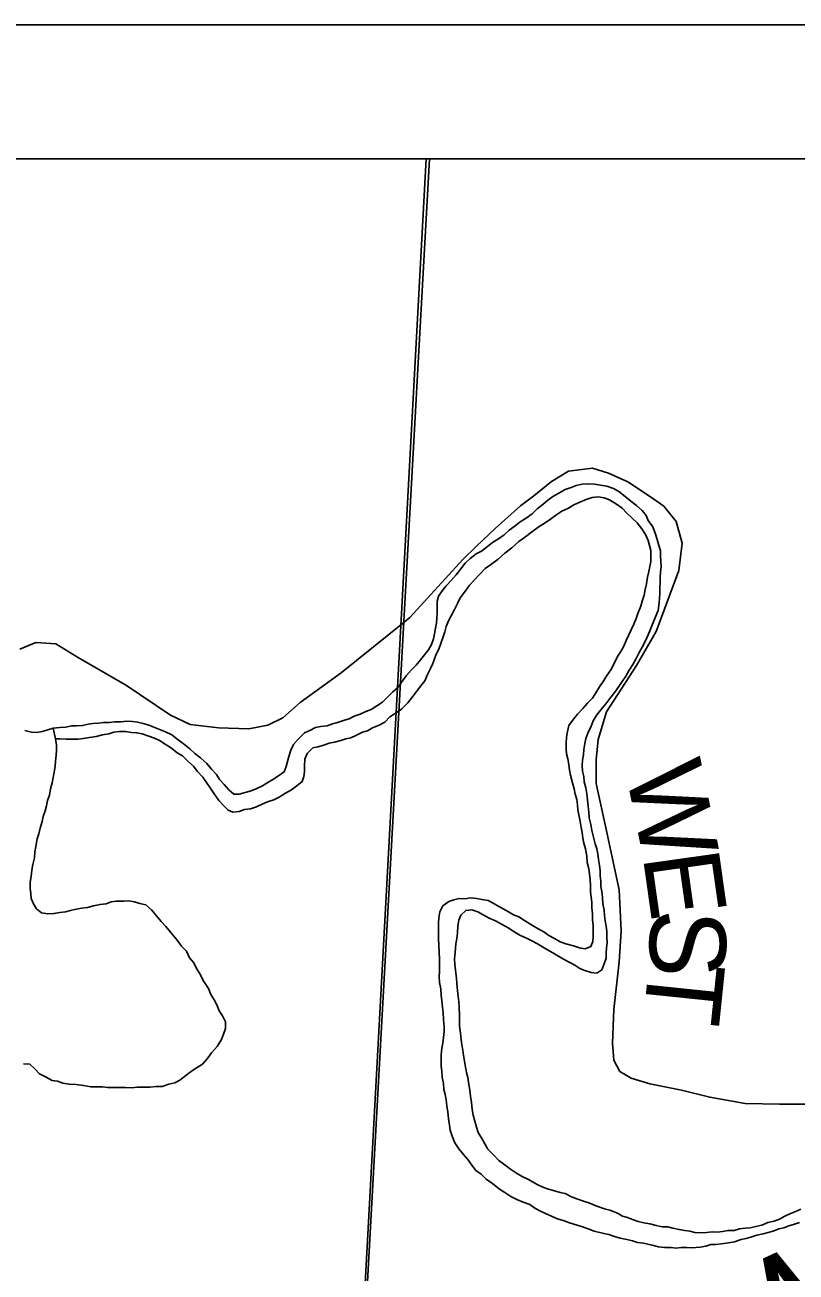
# Model space of a CAD drawing. Extents: x -20.2 to 34, y 0 to 22.
# Drawn here: x 7.849 to 8.424, y 20.069 to 21 of the extents above; entities that cross this region are included whole.
import ezdxf

# ---------------------------------------------------------------- set-up
doc = ezdxf.new("R2010")
doc.units = 0
for name, color, linetype in [('Default', 7, 'Continuous'), ('GM_X_Major_River', 7, 'Continuous'), ('GM_X_Minor_River', 7, 'Continuous'), ('GM_X_Minor_River_Text', 7, 'Continuous'), ('GM_X_Township_Road', 7, 'Continuous'), ('GM_X_Township_Road_Text', 7, 'Continuous'), ('SH_Cut_Line', 7, 'Continuous'), ('SH_Data', 7, 'Continuous')]:
    doc.layers.add(name, color=color, linetype=linetype)

msp = doc.modelspace()

# ---------------------------------------------------------------- linework, layer by layer
at = {"layer": 'Default'}
for points in [[(8.15084, 20.9), (2.1, 20.9), (2.1, 19.2514), (2.92528, 19.19513), (4.08404, 19.12989), (4.12898, 19.12845), (4.49998, 19.10635), (4.57534, 19.10322), (5.07163, 19.0751), (5.61682, 19.0426), (5.62797, 19.04192), (5.90057, 19.02599), (6.53318, 18.99275), (7.38712, 18.94649), (7.53952, 18.93824), (7.80715, 18.91995), (8.043, 18.90974), (8.04849, 19.09144), (8.07091, 19.45221), (8.1316, 20.55479)], [(8.14837, 20.9), (7.0959, 20.9), (7.04086, 20.01146), (8.09719, 19.95555)], [(8.9, 19.92008), (8.9, 20.9), (8.14837, 20.9), (8.09719, 19.95555)]]:
    msp.add_lwpolyline(points, close=True, dxfattribs=at)
msp.add_lwpolyline([(8.9, 14.81759), (8.9, 20.9), (8.15084, 20.9), (8.1316, 20.55479), (8.07091, 19.45221), (8.04849, 19.09144), (8.043, 18.90974), (7.80715, 18.91995), (7.53952, 18.93824), (7.38712, 18.94649), (6.53318, 18.99275), (5.90057, 19.02599), (5.87099, 18.53836), (5.80691, 17.48436), (5.78313, 17.24828), (5.78116, 17.15273), (5.73681, 16.42062)], dxfattribs=at)
at = {"layer": 'GM_X_Major_River'}
for points in [[(8.28122, 20.29949), (8.28269, 20.30368), (8.28265, 20.30748), (8.28298, 20.31129), (8.28332, 20.31509), (8.28327, 20.31889), (8.28321, 20.32383), (8.28279, 20.32762), (8.28199, 20.33142), (8.28156, 20.33559), (8.28113, 20.33938), (8.28031, 20.34431), (8.27988, 20.34887), (8.27945, 20.35342), (8.27864, 20.35721), (8.2786, 20.36101), (8.27817, 20.36519), (8.27813, 20.36899), (8.2777, 20.37278), (8.27689, 20.37733), (8.27646, 20.3815), (8.27565, 20.38529), (8.27447, 20.38908), (8.27327, 20.394), (8.27208, 20.39893), (8.27126, 20.40348), (8.27007, 20.4084), (8.26964, 20.41258), (8.2692, 20.41713), (8.26877, 20.42169), (8.26834, 20.42624), (8.26753, 20.43079), (8.26633, 20.43534), (8.26591, 20.43913), (8.2651, 20.4433), (8.26467, 20.44748), (8.265, 20.45128), (8.26571, 20.45547), (8.26605, 20.45927), (8.26675, 20.46384), (8.26747, 20.46765), (8.26894, 20.47147), (8.27154, 20.47682), (8.27301, 20.48064), (8.27561, 20.48523), (8.2786, 20.48907), (8.28235, 20.4933), (8.28534, 20.49752), (8.28908, 20.50212), (8.29207, 20.50634), (8.29468, 20.51017), (8.29729, 20.514), (8.29989, 20.5186), (8.3025, 20.52281), (8.30473, 20.52664), (8.30733, 20.53161), (8.30956, 20.53582), (8.31216, 20.54041), (8.314, 20.545), (8.31585, 20.5492), (8.31769, 20.55416), (8.31954, 20.55836), (8.32138, 20.56295), (8.3221, 20.56676), (8.32242, 20.5717), (8.32274, 20.57626), (8.3227, 20.58006), (8.32303, 20.58387), (8.32298, 20.58805), (8.32332, 20.59185), (8.32365, 20.59565), (8.32361, 20.59945), (8.32318, 20.60401), (8.32313, 20.60781), (8.32195, 20.61159), (8.32075, 20.61614), (8.31918, 20.62068), (8.31761, 20.6256), (8.31414, 20.63012), (8.31257, 20.63389), (8.30949, 20.63766), (8.30527, 20.6414), (8.30106, 20.64477), (8.29684, 20.64814), (8.29224, 20.65188), (8.28804, 20.65411), (8.28308, 20.65595), (8.27852, 20.65665), (8.27396, 20.65735), (8.2694, 20.65767), (8.26485, 20.65724), (8.2603, 20.65642), (8.25653, 20.65485), (8.25199, 20.65327), (8.24746, 20.65056), (8.24294, 20.64822), (8.23917, 20.64551), (8.23542, 20.64205), (8.23128, 20.63896), (8.22753, 20.63511), (8.22301, 20.63201)], [(8.23258, 20.62567), (8.23635, 20.628), (8.24124, 20.6311), (8.24576, 20.63458), (8.24952, 20.63729), (8.25405, 20.63924), (8.25858, 20.64196), (8.26311, 20.64392), (8.26764, 20.64587), (8.27217, 20.64745), (8.27672, 20.64789), (8.28129, 20.64718), (8.2851, 20.64571), (8.29046, 20.64236), (8.29467, 20.63937), (8.29813, 20.63561), (8.30196, 20.63224), (8.3058, 20.62849), (8.30927, 20.62397), (8.31198, 20.61983), (8.31393, 20.61529), (8.31511, 20.61151), (8.31592, 20.60772), (8.31597, 20.60354), (8.31601, 20.59974), (8.3153, 20.59593), (8.31459, 20.59212), (8.3135, 20.58793), (8.3128, 20.58298), (8.31171, 20.57879), (8.31099, 20.5746), (8.30953, 20.57002), (8.30844, 20.56621), (8.30622, 20.56086), (8.30513, 20.55704), (8.30328, 20.55284), (8.30143, 20.54864), (8.29958, 20.54481), (8.29773, 20.54061), (8.29588, 20.53641), (8.29365, 20.53258), (8.29104, 20.52875), (8.28845, 20.52301), (8.28622, 20.51881), (8.28324, 20.51459), (8.281, 20.51076), (8.27764, 20.50616), (8.27504, 20.50157), (8.27243, 20.49773), (8.26868, 20.49389), (8.26531, 20.49004), (8.26118, 20.48581), (8.25819, 20.48197), (8.25483, 20.47737), (8.25374, 20.4728), (8.25303, 20.46861), (8.25271, 20.46405), (8.25276, 20.45987), (8.25318, 20.45607), (8.25398, 20.45228), (8.25479, 20.44811), (8.25522, 20.44394), (8.25603, 20.44015), (8.25761, 20.43447), (8.2588, 20.42992), (8.25961, 20.42613), (8.2608, 20.42197), (8.26122, 20.41817), (8.26164, 20.41438), (8.26246, 20.40945), (8.26327, 20.40566), (8.26408, 20.40111), (8.26488, 20.39732), (8.26531, 20.39314), (8.26612, 20.38936), (8.2673, 20.38519), (8.26813, 20.37988), (8.26856, 20.37495), (8.26976, 20.3704), (8.27018, 20.36661), (8.27062, 20.36205), (8.27104, 20.35788), (8.2711, 20.35294), (8.27153, 20.34914), (8.27195, 20.34535), (8.272, 20.34117), (8.27243, 20.33661), (8.27249, 20.33206), (8.27291, 20.32826), (8.27296, 20.32408), (8.27301, 20.3199), (8.27268, 20.3161), (8.2712, 20.31228), (8.26705, 20.31071), (8.26286, 20.31142), (8.25829, 20.31288), (8.25258, 20.31433), (8.24839, 20.31579), (8.24418, 20.3184), (8.23998, 20.32063), (8.23615, 20.32324)], [(8.22301, 20.63201), (8.21849, 20.62929), (8.21473, 20.62621), (8.21021, 20.62311), (8.20646, 20.61964), (8.20232, 20.61655), (8.19779, 20.61384), (8.19403, 20.61075), (8.18952, 20.60727), (8.18574, 20.60532), (8.18123, 20.60185), (8.17748, 20.59838), (8.17411, 20.59416), (8.17075, 20.58956), (8.167, 20.58533), (8.16325, 20.58148), (8.16026, 20.57764), (8.15765, 20.57381), (8.15656, 20.57), (8.1566, 20.56582), (8.15666, 20.56126), (8.15632, 20.55746), (8.15599, 20.55365), (8.15528, 20.54984), (8.15457, 20.54565), (8.15385, 20.54184), (8.15238, 20.53765), (8.15015, 20.53382), (8.14716, 20.52998), (8.14417, 20.52614), (8.1408, 20.5223), (8.13705, 20.51845), (8.1333, 20.51423), (8.12994, 20.50963), (8.12733, 20.50579), (8.12357, 20.50232), (8.11944, 20.49847), (8.11569, 20.49463), (8.11155, 20.49191), (8.1074, 20.4892), (8.10325, 20.48763), (8.09909, 20.48568), (8.09456, 20.4841), (8.09078, 20.48215), (8.08662, 20.48096), (8.08209, 20.47939), (8.0783, 20.47858), (8.07452, 20.47701), (8.06959, 20.47657), (8.06581, 20.47576), (8.06203, 20.47381), (8.0575, 20.47186), (8.053, 20.46724), (8.04926, 20.46301), (8.04741, 20.45881), (8.04594, 20.45423), (8.04485, 20.45042), (8.04376, 20.4466), (8.04228, 20.44279), (8.03814, 20.43969), (8.034, 20.43698), (8.03023, 20.43465), (8.02608, 20.43232), (8.02193, 20.43037), (8.01778, 20.42842), (8.01324, 20.42722), (8.0087, 20.42602), (8.0047, 20.42607), (8.00107, 20.42935), (7.9976, 20.43311), (7.99414, 20.43686), (7.99182, 20.44063), (7.98798, 20.44476), (7.98451, 20.4489), (7.97991, 20.45302), (7.97569, 20.45639), (7.97186, 20.45976), (7.96687, 20.46388), (7.96228, 20.46724), (7.95845, 20.47023), (7.95387, 20.47246), (7.95005, 20.47393), (7.94624, 20.4754), (7.94128, 20.47762), (7.93709, 20.4787), (7.9329, 20.47979), (7.9291, 20.48012), (7.92492, 20.48045), (7.92037, 20.48001), (7.91582, 20.47996), (7.91203, 20.47953), (7.90747, 20.47947), (7.90368, 20.47904), (7.89955, 20.47885), (7.8961, 20.47819), (7.89193, 20.47738), (7.88738, 20.47694), (7.88359, 20.47689), (7.87942, 20.47608), (7.87487, 20.47564), (7.86994, 20.4752)], [(7.86994, 20.4752), (7.87156, 20.46724), (7.87497, 20.46729), (7.87953, 20.46696), (7.88408, 20.46702), (7.88864, 20.46708), (7.89243, 20.4675), (7.89697, 20.46832), (7.9019, 20.46914), (7.90682, 20.47034), (7.91137, 20.47116), (7.91515, 20.47235), (7.91932, 20.47278), (7.92387, 20.47284), (7.92844, 20.47214), (7.93224, 20.4718), (7.93642, 20.4711), (7.94061, 20.46963), (7.94557, 20.46779), (7.94939, 20.46594), (7.9536, 20.46333), (7.95818, 20.46035), (7.9624, 20.45698), (7.96648, 20.45459), (7.97045, 20.45062), (7.97467, 20.44688), (7.97737, 20.44311), (7.9816, 20.4386), (7.9843, 20.43484), (7.987, 20.43069), (7.9901, 20.42617), (7.99357, 20.42127), (7.99703, 20.41752), (8.00043, 20.41404), (8.00392, 20.41266), (8.00885, 20.41311), (8.01263, 20.41467), (8.01718, 20.41511), (8.02171, 20.41669), (8.02587, 20.41864), (8.03002, 20.42021), (8.03456, 20.42179), (8.03871, 20.42374), (8.04323, 20.42684), (8.04776, 20.42917), (8.0519, 20.43227), (8.05566, 20.43535), (8.05713, 20.43917), (8.05746, 20.44297), (8.05742, 20.44716), (8.05774, 20.4521), (8.05958, 20.4563), (8.06371, 20.46054), (8.0675, 20.46134), (8.07204, 20.46254), (8.07582, 20.46411), (8.07998, 20.46492), (8.08452, 20.46611), (8.0883, 20.4673), (8.09209, 20.46811), (8.09587, 20.46968), (8.10077, 20.4724), (8.10456, 20.47321), (8.10833, 20.47553), (8.11324, 20.4775), (8.11738, 20.47983), (8.12114, 20.48367), (8.12603, 20.48678), (8.1298, 20.48948), (8.13468, 20.4941), (8.13804, 20.49871), (8.14103, 20.50254), (8.1444, 20.50677), (8.14739, 20.51061), (8.14923, 20.51519), (8.15146, 20.51978), (8.15331, 20.5236), (8.15588, 20.53047), (8.15774, 20.53429), (8.15958, 20.53926), (8.16104, 20.54346), (8.16214, 20.54727), (8.16323, 20.55108), (8.16508, 20.55529), (8.16693, 20.55911), (8.16916, 20.56332), (8.17176, 20.56829), (8.17361, 20.57249), (8.17772, 20.57786), (8.18071, 20.58208), (8.18446, 20.58593), (8.18783, 20.58977), (8.19233, 20.59439), (8.19647, 20.5971), (8.20212, 20.60135), (8.20699, 20.60597), (8.21226, 20.60984), (8.21752, 20.61446), (8.22166, 20.61755), (8.22806, 20.6222), (8.23258, 20.62567)], [(8.23615, 20.32324), (8.23195, 20.32547), (8.22774, 20.32807), (8.22162, 20.3318), (8.21742, 20.33441), (8.2136, 20.33588), (8.20864, 20.33886), (8.20252, 20.3422), (8.19832, 20.3448), (8.1945, 20.34666), (8.18993, 20.34736), (8.18613, 20.34807), (8.18119, 20.34877), (8.1774, 20.34796), (8.17284, 20.34829), (8.16906, 20.3471), (8.16528, 20.34591), (8.16076, 20.34281), (8.15854, 20.33822), (8.15783, 20.33366), (8.15749, 20.32985), (8.15754, 20.32605), (8.1576, 20.32149), (8.15764, 20.3177), (8.15769, 20.31351), (8.15814, 20.30782), (8.15819, 20.30326), (8.15824, 20.2987), (8.1583, 20.29376), (8.15797, 20.28996), (8.1584, 20.2854), (8.15921, 20.28086), (8.15965, 20.27592), (8.16008, 20.27175), (8.16052, 20.26719), (8.16094, 20.26302), (8.16139, 20.2577), (8.16182, 20.25277), (8.16187, 20.24897), (8.16117, 20.2444), (8.16083, 20.24021), (8.16012, 20.23641), (8.15942, 20.23146), (8.15946, 20.22766), (8.15952, 20.2231), (8.15994, 20.2193), (8.16038, 20.21475), (8.16119, 20.2102), (8.16162, 20.20564), (8.16243, 20.20186), (8.16323, 20.19807), (8.16367, 20.19313), (8.16448, 20.18896), (8.16492, 20.18365), (8.16573, 20.1791), (8.16616, 20.1753), (8.16773, 20.17076), (8.16968, 20.16585), (8.17278, 20.16133), (8.17624, 20.15719), (8.17932, 20.15343), (8.18241, 20.14929), (8.18549, 20.14514), (8.18932, 20.14253), (8.19316, 20.13878), (8.19775, 20.13542), (8.20312, 20.13131), (8.20695, 20.12869), (8.21153, 20.12571), (8.21612, 20.12349), (8.22069, 20.12165), (8.22565, 20.11981), (8.22948, 20.1172), (8.23368, 20.11497), (8.2375, 20.11312), (8.24246, 20.1109), (8.24628, 20.10905), (8.25123, 20.10759), (8.25542, 20.10612), (8.26114, 20.1043), (8.26494, 20.1032), (8.26914, 20.10174), (8.27371, 20.09989), (8.28095, 20.09808), (8.28475, 20.09737), (8.28895, 20.0959), (8.29313, 20.09482), (8.29808, 20.09374), (8.30227, 20.09265), (8.30608, 20.09156), (8.31064, 20.09086), (8.31711, 20.08942), (8.32168, 20.08834), (8.32624, 20.08763), (8.33118, 20.0877), (8.33498, 20.08736), (8.33877, 20.08779), (8.34294, 20.08784), (8.34674, 20.08751), (8.35281, 20.08797), (8.35698, 20.08878)], [(8.34889, 20.09894), (8.34507, 20.10003), (8.34128, 20.10036), (8.33709, 20.10107), (8.33252, 20.10215), (8.32871, 20.10324), (8.32454, 20.10319), (8.31997, 20.10427), (8.3154, 20.10536), (8.31084, 20.10606), (8.30665, 20.10715), (8.30246, 20.10861), (8.29865, 20.11009), (8.29484, 20.11118), (8.29102, 20.11341), (8.2853, 20.11562), (8.28149, 20.11671), (8.27577, 20.11854), (8.26967, 20.12112), (8.26586, 20.12221), (8.2609, 20.12405), (8.25671, 20.12552), (8.25212, 20.12812), (8.24832, 20.12884), (8.24413, 20.12992), (8.23956, 20.13139), (8.23537, 20.13285), (8.23117, 20.1347), (8.22467, 20.13842), (8.22009, 20.14064), (8.21588, 20.14325), (8.21129, 20.14623), (8.20631, 20.14997), (8.20249, 20.15258), (8.19826, 20.15709), (8.19441, 20.16122), (8.19209, 20.16499), (8.18977, 20.16914), (8.18705, 20.17367), (8.18587, 20.17745), (8.18468, 20.182), (8.18349, 20.18654), (8.18268, 20.19071), (8.18223, 20.19603), (8.18142, 20.20057), (8.18099, 20.20513), (8.18018, 20.2093), (8.17936, 20.21461), (8.17855, 20.2184), (8.17775, 20.22219), (8.17694, 20.22674), (8.17613, 20.23091), (8.1757, 20.23508), (8.17489, 20.23887), (8.17447, 20.24267), (8.17403, 20.2476), (8.17321, 20.25291), (8.17317, 20.25671), (8.17312, 20.26089), (8.17304, 20.26697), (8.17262, 20.27114), (8.17219, 20.27494), (8.17176, 20.27949), (8.17132, 20.28481), (8.17089, 20.2886), (8.17046, 20.2924), (8.16963, 20.29922), (8.16958, 20.30303), (8.1699, 20.30797), (8.17059, 20.31444), (8.1713, 20.31825), (8.17163, 20.32243), (8.17195, 20.32775), (8.17265, 20.33194), (8.17413, 20.33576), (8.17788, 20.33923), (8.18243, 20.33967), (8.18701, 20.3382), (8.19083, 20.33597), (8.19541, 20.33337), (8.19999, 20.33153), (8.20458, 20.32892), (8.20954, 20.32633), (8.21452, 20.32297), (8.21834, 20.32074), (8.2233, 20.31852), (8.22712, 20.31667), (8.23132, 20.31444), (8.23514, 20.31221), (8.23896, 20.30998), (8.24279, 20.30774), (8.24661, 20.30551), (8.25082, 20.3029), (8.25502, 20.30068), (8.25922, 20.29845), (8.26305, 20.29584), (8.26686, 20.29437), (8.27143, 20.2929), (8.27561, 20.29257), (8.27938, 20.2949), (8.28122, 20.29949)], [(8.42802, 20.11627), (8.42348, 20.11431), (8.41971, 20.11275), (8.41593, 20.11118), (8.41216, 20.10885), (8.408, 20.10728), (8.40346, 20.10646), (8.39892, 20.1045), (8.39438, 20.10331), (8.39022, 20.1025), (8.38643, 20.10207), (8.38226, 20.10164), (8.3781, 20.10044), (8.37354, 20.10039), (8.36976, 20.09958), (8.36559, 20.09915), (8.36179, 20.09948), (8.35762, 20.09905), (8.35382, 20.09862), (8.34889, 20.09894)], [(8.35698, 20.08878), (8.36076, 20.08996), (8.36455, 20.09001), (8.36872, 20.09045), (8.37403, 20.09127), (8.37857, 20.09209), (8.38349, 20.09367), (8.38728, 20.09448), (8.39144, 20.09567), (8.39522, 20.09686), (8.39976, 20.09806), (8.40355, 20.09886), (8.40733, 20.10005), (8.41149, 20.10162), (8.41527, 20.10243), (8.41905, 20.104), (8.42321, 20.10519), (8.42699, 20.10638)]]:
    msp.add_lwpolyline(points, dxfattribs=at)
at = {"layer": 'GM_X_Minor_River'}
for points in [[(7.84871, 20.47342), (7.85365, 20.47234), (7.85745, 20.472), (7.862, 20.47282), (7.86994, 20.4752)], [(7.86589, 20.33683), (7.86132, 20.33754), (7.85749, 20.34053), (7.85517, 20.3443), (7.8536, 20.34808), (7.85318, 20.35187), (7.85276, 20.35567), (7.8527, 20.36022), (7.85341, 20.36479), (7.85411, 20.36936), (7.85482, 20.37355), (7.8559, 20.37851), (7.85623, 20.38307), (7.85694, 20.38688), (7.85801, 20.39259), (7.85911, 20.3964), (7.8602, 20.4006), (7.86166, 20.40556), (7.86237, 20.40937), (7.86384, 20.41357), (7.86493, 20.41738), (7.86565, 20.42119), (7.86711, 20.42539), (7.86782, 20.42995), (7.86928, 20.43453), (7.87, 20.43834), (7.87071, 20.44253), (7.87142, 20.44672), (7.87175, 20.45052), (7.87208, 20.45509), (7.87241, 20.45889), (7.87237, 20.46269), (7.87156, 20.46724)], [(7.84785, 20.22489), (7.85241, 20.22456), (7.85624, 20.22119), (7.85971, 20.21743), (7.86467, 20.21484), (7.86926, 20.21224), (7.87306, 20.2119), (7.87725, 20.21043), (7.88181, 20.20973), (7.88713, 20.20942), (7.89245, 20.20873), (7.89816, 20.20766), (7.90233, 20.20771), (7.90651, 20.20776), (7.91069, 20.20706), (7.91525, 20.20711), (7.91904, 20.20716), (7.92398, 20.20722), (7.92853, 20.2069), (7.93271, 20.20733), (7.9384, 20.2074), (7.94219, 20.20745), (7.94674, 20.20789), (7.9513, 20.20795), (7.95621, 20.20953), (7.96076, 20.21072), (7.96453, 20.21267), (7.96904, 20.21615), (7.97318, 20.21924), (7.97733, 20.22195), (7.98147, 20.22466), (7.98484, 20.22851), (7.9882, 20.23311), (7.99232, 20.23772), (7.99567, 20.24308), (7.99715, 20.2469), (7.99862, 20.2511), (7.99856, 20.25604), (7.99623, 20.26057), (7.99391, 20.26434), (7.99196, 20.26887), (7.99001, 20.27265), (7.98769, 20.27642), (7.98574, 20.28096), (7.98187, 20.28699), (7.97992, 20.29114), (7.97683, 20.29604), (7.97488, 20.3002), (7.9718, 20.30396), (7.96947, 20.30887), (7.96562, 20.31263), (7.96253, 20.31714), (7.95753, 20.32316), (7.95406, 20.3273), (7.9506, 20.33106), (7.94714, 20.33519), (7.94329, 20.3397), (7.93907, 20.34345), (7.9345, 20.34453), (7.93069, 20.34563), (7.92651, 20.34633), (7.92271, 20.34629), (7.91702, 20.34621), (7.91323, 20.34579), (7.90945, 20.34422), (7.9049, 20.34378), (7.89998, 20.34258), (7.89544, 20.34138), (7.89127, 20.34095), (7.8871, 20.34014), (7.88294, 20.33933), (7.87916, 20.33814), (7.87499, 20.33771), (7.87044, 20.33689), (7.86589, 20.33683)]]:
    msp.add_lwpolyline(points, dxfattribs=at)
at = {"layer": 'GM_X_Township_Road'}
for points in [[(8.43787, 20.19467), (8.41213, 20.19467), (8.3864, 20.19532), (8.36002, 20.19988), (8.33885, 20.20509), (8.3154, 20.20998), (8.30139, 20.21421), (8.29292, 20.2191), (8.28836, 20.22757), (8.28739, 20.24027), (8.28836, 20.26535), (8.29227, 20.30085), (8.2939, 20.32398), (8.29227, 20.3546), (8.28283, 20.39856), (8.27533, 20.43407), (8.27533, 20.45166), (8.27678, 20.46669), (8.28283, 20.48749), (8.30525, 20.52203), (8.31995, 20.54742), (8.33699, 20.59301), (8.3395, 20.61321), (8.33494, 20.6295), (8.32582, 20.6409), (8.31574, 20.6479), (8.29878, 20.65914), (8.28445, 20.66561), (8.2724, 20.66923), (8.25449, 20.66695), (8.24198, 20.65926), (8.22876, 20.64872), (8.21866, 20.64122), (8.19977, 20.62429), (8.186, 20.61107)], [(8.186, 20.61107), (8.17567, 20.60116), (8.13625, 20.55784), (8.13181, 20.55427), (8.08479, 20.51648), (8.0544, 20.49434), (8.04147, 20.48293), (8.03007, 20.47739), (8.01607, 20.47478), (7.99326, 20.47543), (7.97209, 20.47804), (7.95744, 20.48498), (7.92454, 20.50703), (7.88806, 20.5282), (7.87185, 20.53811), (7.8571, 20.53929), (7.845, 20.53424)]]:
    msp.add_lwpolyline(points, dxfattribs=at)
at = {"layer": 'SH_Cut_Line'}
msp.add_lwpolyline([(5.77351, 14.1), (8.9, 14.1), (8.9, 20.9), (2.1, 20.9), (2.1, 14.1), (5.39535, 14.1), (5.72679, 14.10759)], close=True, dxfattribs=at)
at = {"layer": 'SH_Data'}
for p, q in [((2, 21), (9, 21)), ((2.1, 20.9), (8.9, 20.9))]:
    msp.add_line(p, q, dxfattribs=at)

# ---------------------------------------------------------------- texts
at = {"layer": 'GM_X_Minor_River_Text'}
msp.add_text('West', height=0.094698, rotation=24.86796, dxfattribs=at).set_placement((8.39029, 19.97079))
at = {"layer": 'GM_X_Township_Road_Text'}
for s, rotation, p in [('W', 281.52589, (8.29689, 20.44379)), ('E', 278.0489, (8.30989, 20.38018)), ('S', 268.9404, (8.31569, 20.34048)), ('T', 264.10135, (8.31506, 20.30342))]:
    msp.add_text(s, height=0.05682, rotation=rotation, dxfattribs=at).set_placement(p)

doc.saveas('drawing.dxf')
